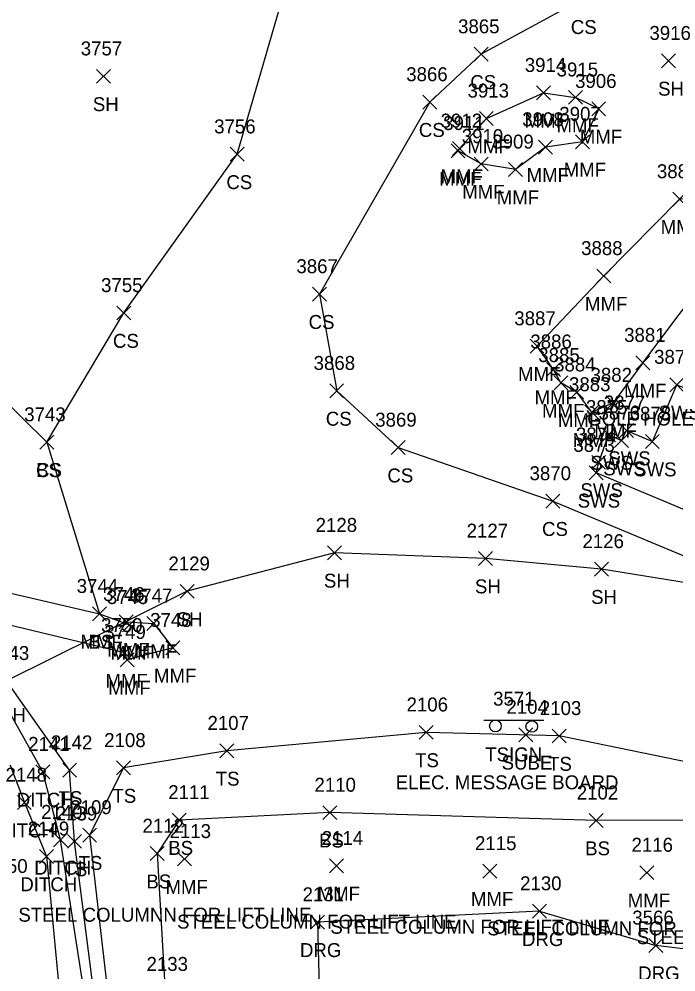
# Model space of a CAD drawing. Extents: x 49137 to 50946, y 9590 to 10709.
# Drawn here: x 49965.3 to 50059.5, y 10186.5 to 10323.2 of the extents above; entities that cross this region are included whole.
import ezdxf

# ---------------------------------------------------------------- set-up
doc = ezdxf.new("R2010")
doc.units = 0
for name, color, linetype in [('D_A', 7, 'Continuous'), ('D_I', 7, 'Continuous'), ('D_TIC', 7, 'Continuous'), ('DD', 7, 'Continuous'), ('L_A', 7, 'Continuous'), ('L_C', 7, 'Continuous'), ('L_I', 7, 'Continuous'), ('L_TIC', 7, 'Continuous'), ('LDEFAULT', 7, 'Continuous'), ('LELB', 7, 'Continuous'), ('LSOGP', 7, 'Continuous'), ('R_A', 7, 'Continuous'), ('R_I', 7, 'Continuous'), ('R_TIC', 7, 'Continuous'), ('RDG', 7, 'Continuous'), ('RSW', 7, 'Continuous'), ('S_A', 7, 'Continuous'), ('S_C', 7, 'Continuous'), ('S_I', 7, 'Continuous'), ('SSGN', 7, 'Continuous'), ('U_A', 7, 'Continuous'), ('U_I', 7, 'Continuous'), ('U_TIC', 7, 'Continuous')]:
    doc.layers.add(name, color=color, linetype=linetype)

msp = doc.modelspace()

# ---------------------------------------------------------------- linework, layer by layer
at = {"layer": 'D_TIC'}
for points in [[(49967.69, 10214.24), (49969.69, 10216.24)], [(49969.69, 10214.24), (49967.69, 10216.24)], [(49965.02, 10209.83), (49967.02, 10211.83)], [(49967.02, 10209.83), (49965.02, 10211.83)], [(49970.2, 10204.48), (49972.2, 10206.48)], [(49972.2, 10204.48), (49970.2, 10206.48)], [(49968.21, 10202.1), (49970.21, 10204.1)], [(49970.21, 10202.1), (49968.21, 10204.1)]]:
    msp.add_lwpolyline(points, dxfattribs=at)
at = {"layer": 'DD'}
for points in [[(49984.26, 10173.72), (49979.3, 10173.63), (49975.22, 10179.6), (49971.2, 10205.48), (49968.69, 10215.24), (49961.84, 10227.4)], [(49959.95, 10226.49), (49966.02, 10210.83), (49969.21, 10203.1), (49971.52, 10178.36), (49977.72, 10168.94)]]:
    msp.add_lwpolyline(points, dxfattribs=at)
at = {"layer": 'L_TIC'}
for points in [[(50030.57, 10317.2), (50032.57, 10319.2)], [(50032.57, 10317.2), (50030.57, 10319.2)], [(50057.47, 10316.25), (50059.47, 10318.25)], [(50059.47, 10316.25), (50057.47, 10318.25)], [(49976.37, 10314.03), (49978.37, 10316.03)], [(49978.37, 10314.03), (49976.37, 10316.03)], [(50039.52, 10311.66), (50041.52, 10313.66)], [(50041.52, 10311.66), (50039.52, 10313.66)], [(50044.1, 10311.01), (50046.1, 10313.01)], [(50046.1, 10311.01), (50044.1, 10313.01)], [(50044.1, 10311.01), (50046.1, 10313.01)], [(50046.1, 10311.01), (50044.1, 10313.01)], [(50023.19, 10310.33), (50025.19, 10312.33)], [(50025.19, 10310.33), (50023.19, 10312.33)], [(50047.44, 10309.36), (50049.44, 10311.36)], [(50049.44, 10309.36), (50047.44, 10311.36)], [(50047.44, 10309.36), (50049.44, 10311.36)], [(50049.44, 10309.36), (50047.44, 10311.36)], [(50031.32, 10307.98), (50033.32, 10309.98)], [(50033.32, 10307.98), (50031.32, 10309.98)], [(50045.13, 10304.64), (50047.13, 10306.64)], [(50047.13, 10304.64), (50045.13, 10306.64)], [(49995.57, 10302.84), (49997.57, 10304.84)], [(49997.57, 10302.84), (49995.57, 10304.84)], [(50027.25, 10303.32), (50029.25, 10305.32)], [(50029.25, 10303.32), (50027.25, 10305.32)], [(50027.45, 10303.67), (50029.45, 10305.67)], [(50029.45, 10303.67), (50027.45, 10305.67)], [(50039.8, 10303.86), (50041.8, 10305.86)], [(50041.8, 10303.86), (50039.8, 10305.86)], [(50030.57, 10301.45), (50032.57, 10303.45)], [(50032.57, 10301.45), (50030.57, 10303.45)], [(50035.52, 10300.66), (50037.52, 10302.66)], [(50037.52, 10300.66), (50035.52, 10302.66)], [(50059.06, 10296.41), (50061.06, 10298.41)], [(50061.06, 10296.41), (50059.06, 10298.41)], [(50048.18, 10285.38), (50050.18, 10287.38)], [(50050.18, 10285.38), (50048.18, 10287.38)], [(50007.37, 10282.78), (50009.37, 10284.78)], [(50009.37, 10282.78), (50007.37, 10284.78)], [(49979.29, 10280.07), (49981.29, 10282.07)], [(49981.29, 10280.07), (49979.29, 10282.07)], [(50038.59, 10275.31), (50040.59, 10277.31)], [(50040.59, 10275.31), (50038.59, 10277.31)], [(50053.78, 10272.92), (50055.78, 10274.92)], [(50055.78, 10272.92), (50053.78, 10274.92)], [(50053.78, 10272.92), (50055.78, 10274.92)], [(50055.78, 10272.92), (50053.78, 10274.92)], [(50040.95, 10271.98), (50042.95, 10273.98)], [(50042.95, 10271.98), (50040.95, 10273.98)], [(50042.03, 10270.03), (50044.03, 10272.03)], [(50044.03, 10270.03), (50042.03, 10272.03)], [(50009.84, 10268.9), (50011.84, 10270.9)], [(50011.84, 10268.9), (50009.84, 10270.9)], [(50044.3, 10268.69), (50046.3, 10270.69)], [(50046.3, 10268.69), (50044.3, 10270.69)], [(50049.53, 10267.19), (50051.53, 10269.19)], [(50051.53, 10267.19), (50049.53, 10269.19)], [(50046.44, 10265.85), (50048.44, 10267.85)], [(50048.44, 10265.85), (50046.44, 10267.85)], [(49968.26, 10261.53), (49970.26, 10263.53)], [(49970.26, 10261.53), (49968.26, 10263.53)], [(49968.26, 10261.53), (49970.26, 10263.53)], [(49970.26, 10261.53), (49968.26, 10263.53)], [(50018.68, 10260.76), (50020.68, 10262.76)], [(50020.68, 10260.76), (50018.68, 10262.76)], [(50040.87, 10253.08), (50042.87, 10255.08)], [(50042.87, 10253.08), (50040.87, 10255.08)], [(50009.52, 10245.66), (50011.52, 10247.66)], [(50011.52, 10245.66), (50009.52, 10247.66)], [(50031.19, 10244.84), (50033.19, 10246.84)], [(50033.19, 10244.84), (50031.19, 10246.84)], [(50047.86, 10243.33), (50049.86, 10245.33)], [(50049.86, 10243.33), (50047.86, 10245.33)], [(49988.39, 10240.13), (49990.39, 10242.13)], [(49990.39, 10240.13), (49988.39, 10242.13)], [(49975.79, 10236.9), (49977.79, 10238.9)], [(49977.79, 10236.9), (49975.79, 10238.9)], [(49975.79, 10236.9), (49977.79, 10238.9)], [(49977.79, 10236.9), (49975.79, 10238.9)], [(49979.64, 10235.74), (49981.64, 10237.74)], [(49981.64, 10235.74), (49979.64, 10237.74)], [(49980.12, 10235.31), (49982.12, 10237.31)], [(49982.12, 10235.31), (49980.12, 10237.31)], [(49983.58, 10235.53), (49985.58, 10237.53)], [(49985.58, 10235.53), (49983.58, 10237.53)], [(49986.33, 10232.02), (49988.33, 10234.02)], [(49988.33, 10232.02), (49986.33, 10234.02)], [(49979.38, 10231.29), (49981.38, 10233.29)], [(49981.38, 10231.29), (49979.38, 10233.29)], [(49979.77, 10230.3), (49981.77, 10232.3)], [(49981.77, 10230.3), (49979.77, 10232.3)], [(50022.69, 10219.9), (50024.69, 10221.9)], [(50024.69, 10219.9), (50022.69, 10221.9)], [(50041.77, 10219.38), (50043.77, 10221.38)], [(50043.77, 10219.38), (50041.77, 10221.38)], [(49994.07, 10217.25), (49996.07, 10219.25)], [(49996.07, 10217.25), (49994.07, 10219.25)], [(49971.52, 10214.46), (49973.52, 10216.46)], [(49973.52, 10214.46), (49971.52, 10216.46)], [(49979.25, 10214.79), (49981.25, 10216.79)], [(49981.25, 10214.79), (49979.25, 10216.79)], [(50008.86, 10208.38), (50010.86, 10210.38)], [(50010.86, 10208.38), (50008.86, 10210.38)], [(49987.23, 10207.32), (49989.23, 10209.32)], [(49989.23, 10207.32), (49987.23, 10209.32)], [(50047.06, 10207.26), (50049.06, 10209.26)], [(50049.06, 10207.26), (50047.06, 10209.26)], [(49972.22, 10204.26), (49974.22, 10206.26)], [(49974.22, 10204.26), (49972.22, 10206.26)], [(49974.39, 10205.16), (49976.39, 10207.16)], [(49976.39, 10205.16), (49974.39, 10207.16)], [(49984.09, 10202.5), (49986.09, 10204.5)], [(49986.09, 10202.5), (49984.09, 10204.5)], [(49984.09, 10202.5), (49986.09, 10204.5)], [(49986.09, 10202.5), (49984.09, 10204.5)], [(49987.99, 10201.73), (49989.99, 10203.73)], [(49989.99, 10201.73), (49987.99, 10203.73)], [(50009.81, 10200.74), (50011.81, 10202.74)], [(50011.81, 10200.74), (50009.81, 10202.74)], [(50031.82, 10200), (50033.82, 10202)], [(50033.82, 10200), (50031.82, 10202)], [(50054.33, 10199.77), (50056.33, 10201.77)], [(50056.33, 10199.77), (50054.33, 10201.77)]]:
    msp.add_lwpolyline(points, dxfattribs=at)
at = {"layer": 'LDEFAULT'}
for points in [[(50048.44, 10310.36), (50046.13, 10305.64), (50040.8, 10304.86), (50036.52, 10301.66), (50031.57, 10302.45), (50028.25, 10304.32), (50028.45, 10304.67), (50032.32, 10308.98), (50040.52, 10312.66), (50045.1, 10312.01)], [(50048.44, 10310.36), (50045.1, 10312.01)], [(50054.78, 10273.92), (50050.53, 10268.19), (50047.44, 10266.85), (50045.3, 10269.69), (50043.03, 10271.03), (50041.95, 10272.98), (50039.59, 10276.31), (50049.18, 10286.38), (50060.06, 10297.41), (50062.82, 10297.9), (50065.54, 10300.23), (50069.58, 10300.04), (50071.42, 10296.35), (50065.05, 10287.61)], [(50054.78, 10273.92), (50065.05, 10287.61)], [(49926.25, 10249.5), (49945.47, 10244.99), (49950.08, 10244.28), (49955.29, 10243.85), (49958.68, 10242.13), (49976.79, 10237.9), (49981.12, 10236.31), (49980.64, 10236.74), (49984.58, 10236.53), (49987.33, 10233.02), (49980.77, 10231.3), (49980.38, 10232.29), (49960.7, 10237.06), (49957.39, 10237.87), (49954.67, 10238.49), (49948.91, 10239.74)]]:
    msp.add_lwpolyline(points, dxfattribs=at)
at = {"layer": 'LELB'}
for points in [[(49968.85, 10355.12), (49955.47, 10336.04), (49948.52, 10322.54), (49945.71, 10295.25), (49955.23, 10276.32), (49969.26, 10262.53), (49976.79, 10237.9)], [(49969.26, 10262.53), (49980.29, 10281.07), (49996.57, 10303.84), (50004.62, 10331.68), (50015.38, 10331.21), (50028.18, 10342.07), (50046.03, 10345.93)], [(50066.26, 10337.75), (50046, 10326.1), (50031.57, 10318.2), (50024.19, 10311.33), (50008.37, 10283.78), (50010.84, 10269.9), (50019.68, 10261.76), (50041.87, 10254.08), (50068.2, 10243.09)], [(50070.14, 10189.73), (50073.04, 10198.84), (50071.51, 10210.93), (50064.89, 10215.85), (50042.77, 10220.38), (50023.69, 10220.9), (49995.07, 10218.25), (49980.25, 10215.79), (49975.39, 10206.16), (49978.31, 10180.83), (49976.37, 10180.49), (49973.22, 10205.26), (49972.52, 10215.46), (49963.46, 10228.28)], [(50066.64, 10189.74), (50064.98, 10208.32), (50048.06, 10208.26), (50009.86, 10209.38), (49988.23, 10208.32), (49985.09, 10203.5)], [(49985.09, 10203.5), (49986.24, 10183.67), (49984.26, 10173.72), (49977.72, 10168.94), (49979.03, 10161.95), (49972.59, 10151.22)]]:
    msp.add_lwpolyline(points, dxfattribs=at)
at = {"layer": 'LSOGP'}
msp.add_lwpolyline([(50112.88, 10184.8), (50111, 10191.05), (50108.59, 10193.82), (50108.42, 10194.29), (50115.92, 10212.32), (50113.93, 10224.33), (50084.34, 10234.53), (50067.52, 10241.32), (50048.86, 10244.33), (50032.18, 10245.84), (50010.52, 10246.66), (49989.39, 10241.14), (49963.46, 10228.29), (49961.84, 10227.4), (49959.95, 10226.5), (49955.98, 10224.67), (49933.01, 10213.1), (49921.15, 10210.06), (49900.78, 10179.13)], dxfattribs=at)
at = {"layer": 'R_TIC'}
for points in [[(50058.66, 10269.78), (50060.66, 10271.78)], [(50060.66, 10269.78), (50058.66, 10271.78)], [(50051.44, 10263.22), (50053.44, 10265.22)], [(50053.44, 10263.22), (50051.44, 10265.22)], [(50048.87, 10262.57), (50050.87, 10264.57)], [(50050.87, 10262.57), (50048.87, 10264.57)], [(50050.73, 10261.78), (50052.73, 10263.78)], [(50052.73, 10261.78), (50050.73, 10263.78)], [(50055.14, 10261.63), (50057.14, 10263.63)], [(50057.14, 10261.63), (50055.14, 10263.63)], [(50047.44, 10258.64), (50049.44, 10260.64)], [(50049.44, 10258.64), (50047.44, 10260.64)], [(50047.06, 10257.15), (50049.06, 10259.15)], [(50049.06, 10257.15), (50047.06, 10259.15)], [(50038.94, 10194.24), (50040.94, 10196.24)], [(50040.94, 10194.24), (50038.94, 10196.24)], [(50007.08, 10192.66), (50009.08, 10194.66)], [(50009.08, 10192.66), (50007.08, 10194.66)], [(50055.63, 10189.32), (50057.63, 10191.32)], [(50057.63, 10189.32), (50055.63, 10191.32)]]:
    msp.add_lwpolyline(points, dxfattribs=at)
at = {"layer": 'RDG'}
for points in [[(50039.94, 10195.24), (50008.08, 10193.66), (50008.46, 10178.52), (50022.06, 10177.27)], [(50039.94, 10195.24), (50056.63, 10190.32)], [(50069.11, 10188.77), (50056.63, 10190.32)]]:
    msp.add_lwpolyline(points, dxfattribs=at)
at = {"layer": 'RSW'}
msp.add_lwpolyline([(50070.45, 10248.77), (50048.06, 10258.15), (50048.44, 10259.64), (50049.87, 10263.57), (50051.73, 10262.78), (50052.44, 10264.22), (50056.14, 10262.63), (50059.66, 10270.78), (50076.84, 10264.18)], dxfattribs=at)
at = {"layer": 'SSGN'}
for p, q in [((50031.96, 10222.65), (50040.56, 10222.65)), ((50035.98, 10221.74), (50035.98, 10221.74))]:
    msp.add_line(p, q, dxfattribs=at)
for centre in [(50033.62, 10221.81), (50038.84, 10221.74)]:
    msp.add_circle(centre, 0.833, dxfattribs=at)
at = {"layer": 'U_TIC'}
for points in [[(50036.97, 10219.56), (50038.97, 10221.56)], [(50038.97, 10219.56), (50036.97, 10221.56)]]:
    msp.add_lwpolyline(points, dxfattribs=at)

# ---------------------------------------------------------------- texts
at = {"layer": 'D_A'}
for p in [(49958.08, 10222.4), (49964.93, 10210.24), (49962.25, 10205.83), (49967.44, 10200.48), (49965.44, 10198.1)]:
    msp.add_text('DITCH', height=2, dxfattribs=at).set_placement(p)
at = {"layer": 'D_I'}
for s, p in [('2141', (49966.57, 10218.24)), ('2148', (49963.32, 10213.83)), ('2140', (49968.42, 10208.48)), ('2149', (49966.51, 10206.1))]:
    msp.add_text(s, height=2, dxfattribs=at).set_placement(p)
at = {"layer": 'L_A'}
for s, p in [('CS', (50044.44, 10321.1)), ('CS', (50030.01, 10313.2)), ('SH', (50056.96, 10312.25)), ('SH', (49975.85, 10310.03)), ('MMF', (50037.81, 10307.66)), ('MMF', (50042.38, 10307.01)), ('MMF', (50042.38, 10307.01)), ('CS', (50022.63, 10306.33)), ('MMF', (50045.73, 10305.36)), ('MMF', (50045.73, 10305.36)), ('MMF', (50029.6, 10303.98)), ('MMF', (50043.41, 10300.64)), ('CS', (49995.01, 10298.84)), ('MMF', (50025.54, 10299.32)), ('MMF', (50025.74, 10299.67)), ('MMF', (50038.09, 10299.86)), ('MMF', (50028.85, 10297.45)), ('MMF', (50033.8, 10296.66)), ('MMF', (50057.34, 10292.41)), ('MMF', (50046.47, 10281.38)), ('CS', (50006.81, 10278.78)), ('CS', (49978.74, 10276.07)), ('MMF', (50036.87, 10271.31)), ('MMF', (50052.07, 10268.92)), ('MMF', (50052.07, 10268.92)), ('MMF', (50039.23, 10267.98)), ('MMF', (50040.31, 10266.03)), ('CS', (50009.28, 10264.9)), ('MMF', (50042.58, 10264.69)), ('MMF', (50047.82, 10263.19)), ('MMF', (50044.72, 10261.85)), ('CS', (49967.7, 10257.53)), ('BS', (49967.7, 10257.53)), ('CS', (50018.12, 10256.76)), ('CS', (50040.31, 10249.08)), ('SH', (50009.01, 10241.66)), ('SH', (50030.68, 10240.84)), ('SH', (50047.35, 10239.33)), ('SH', (49987.88, 10236.13)), ('BS', (49975.23, 10232.9)), ('MMF', (49974.07, 10232.9)), ('MMF', (49977.92, 10231.74)), ('MMF', (49978.4, 10231.31)), ('MMF', (49981.86, 10231.53)), ('MMF', (49984.62, 10228.02)), ('MMF', (49977.66, 10227.29)), ('MMF', (49978.06, 10226.3)), ('TS', (50022.1, 10215.9)), ('TS', (50041.18, 10215.38)), ('TS', (49993.48, 10213.25)), ('TS', (49970.93, 10210.46)), ('TS', (49978.66, 10210.79)), ('BS', (50008.3, 10204.38)), ('BS', (49986.67, 10203.32)), ('BS', (50046.5, 10203.26)), ('TS', (49971.63, 10200.26)), ('TS', (49973.8, 10201.16)), ('BS', (49983.53, 10198.5)), ('BS', (49983.53, 10198.5)), ('MMF', (49986.27, 10197.73)), ('MMF', (50008.1, 10196.74)), ('MMF', (50030.1, 10196)), ('MMF', (50052.61, 10195.77))]:
    msp.add_text(s, height=2, dxfattribs=at).set_placement(p)
at = {"layer": 'L_C'}
for s, p in [('GOLF HOLE', (50046.79, 10264.92)), ('GOLF HOLE', (50046.79, 10264.92)), ('STEEL COLUMNN FOR LIFT LINE', (49965.16, 10193.73)), ('STEEL COLUMN FOR LIFT LINE', (49987.93, 10192.74)), ('STEEL COLUMN FOR LIFT LINE', (50009.93, 10192)), ('STEEL COLUMN FOR LIFT LINE', (50032.45, 10191.77)), ('STEEL COLUMN FOR LIFT LINE', (50053.9, 10190.51))]:
    msp.add_text(s, height=2, dxfattribs=at).set_placement(p)
at = {"layer": 'L_I'}
for s, p in [('3865', (50028.26, 10321.2)), ('3916', (50055.72, 10320.25)), ('3757', (49974.11, 10318.03)), ('3914', (50037.83, 10315.66)), ('3915', (50042.4, 10315.01)), ('3915', (50042.4, 10315.01)), ('3866', (50020.82, 10314.33)), ('3906', (50045.05, 10313.36)), ('3906', (50045.05, 10313.36)), ('3913', (50029.62, 10311.98)), ('3907', (50042.79, 10308.64)), ('3756', (49993.26, 10306.84)), ('3912', (50025.76, 10307.67)), ('3911', (50026.13, 10307.32)), ('3908', (50037.47, 10307.86)), ('3910', (50028.79, 10305.45)), ('3909', (50033.17, 10304.66)), ('3889', (50056.79, 10300.41)), ('3888', (50045.92, 10289.38)), ('3867', (50005.06, 10286.78)), ('3755', (49977.03, 10284.07)), ('3887', (50036.33, 10279.31)), ('3881', (50052.09, 10276.92)), ('3881', (50052.09, 10276.92)), ('3886', (50038.63, 10275.98)), ('3885', (50039.77, 10274.03)), ('3868', (50007.53, 10272.9)), ('3884', (50042.04, 10272.69)), ('3882', (50047.27, 10271.19)), ('3883', (50044.18, 10269.85)), ('3743', (49966, 10265.53)), ('3743', (49966, 10265.53)), ('3869', (50016.37, 10264.76)), ('3870', (50038.52, 10257.08)), ('2128', (50007.82, 10249.66)), ('2127', (50029.49, 10248.84)), ('2126', (50046.11, 10247.33)), ('2129', (49986.69, 10244.13)), ('3744', (49973.53, 10240.9)), ('3744', (49973.53, 10240.9)), ('3746', (49977.32, 10239.74)), ('3745', (49977.86, 10239.31)), ('3747', (49981.32, 10239.53)), ('3748', (49984.07, 10236.02)), ('3750', (49977.03, 10235.29)), ('3749', (49977.5, 10234.3)), ('2143', (49960.77, 10231.28)), ('2106', (50020.87, 10223.9)), ('2103', (50040, 10223.38)), ('2107', (49992.3, 10221.25)), ('2142', (49969.83, 10218.46)), ('2108', (49977.48, 10218.79)), ('2111', (49986.67, 10211.32)), ('2110', (50007.65, 10212.38)), ('2102', (50045.29, 10211.26)), ('2109', (49972.61, 10209.16)), ('2139', (49970.52, 10208.26)), ('2112', (49982.97, 10206.5)), ('2112', (49982.97, 10206.5)), ('2113', (49986.86, 10205.73)), ('2114', (50008.69, 10204.74)), ('2115', (50030.69, 10204)), ('2116', (50053.15, 10203.77)), ('2150', (49960.54, 10200.72)), ('2133', (49983.55, 10186.67))]:
    msp.add_text(s, height=2, dxfattribs=at).set_placement(p)
at = {"layer": 'R_A'}
for s, p in [('SWS', (50057.03, 10265.78)), ('SWS', (50049.81, 10259.22)), ('SWS', (50047.24, 10258.57)), ('SWS', (50049.1, 10257.78)), ('SWS', (50053.51, 10257.63)), ('SWS', (50045.81, 10254.64)), ('SWS', (50045.43, 10253.15)), ('DRG', (50037.43, 10190.24)), ('DRG', (50005.57, 10188.66)), ('DRG', (50054.11, 10185.32))]:
    msp.add_text(s, height=2, dxfattribs=at).set_placement(p)
at = {"layer": 'R_I'}
for s, p in [('3879', (50056.39, 10273.78)), ('3877', (50049.18, 10267.22)), ('3875', (50046.61, 10266.57)), ('3876', (50048.42, 10265.78)), ('3878', (50052.88, 10265.63)), ('3874', (50045.18, 10262.64)), ('3873', (50044.8, 10261.15)), ('2130', (50037.16, 10198.24)), ('2131', (50005.95, 10196.66)), ('3566', (50053.26, 10193.32))]:
    msp.add_text(s, height=2, dxfattribs=at).set_placement(p)
at = {"layer": 'S_A'}
msp.add_text('TSIGN', height=2, dxfattribs=at).set_placement((50032.16, 10216.73))
at = {"layer": 'S_C'}
msp.add_text('ELEC. MESSAGE BOARD', height=2, dxfattribs=at).set_placement((50019.32, 10212.73))
at = {"layer": 'S_I'}
msp.add_text('3571', height=2, dxfattribs=at).set_placement((50033.29, 10224.73))
at = {"layer": 'U_A'}
msp.add_text('SUBE', height=2, dxfattribs=at).set_placement((50034.51, 10215.56))
at = {"layer": 'U_I'}
msp.add_text('2104', height=2, dxfattribs=at).set_placement((50035.2, 10223.56))

doc.saveas('drawing.dxf')
